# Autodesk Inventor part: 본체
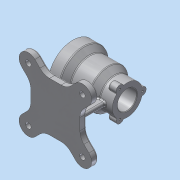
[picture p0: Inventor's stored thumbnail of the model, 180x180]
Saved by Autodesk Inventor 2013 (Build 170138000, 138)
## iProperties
Created: 2017-03
Part Number: 본체
Material: 알루미늄 6061
Document SubType Name: Modeling
Designer: Administrator
Density: 2.71 g/cm^3
Mass: 1008.07 g
Surface Area: 842.343 cm^2
Volume: 371.982 cm^3
Author: Administrator
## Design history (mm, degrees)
sketch "스케치1"
  geometry: L1 (-50, 0)-(50, 0); L2 (-50, 45)-(-30, 45); L3 (-30, 45)-(-19, 36); L4 (-19, 36)-(15, 36); L5 (15, 36)-(27, 27.5); L6 (27, 27.5)-(50, 27.5); L7 (50, 27.5)-(50, 17.5); L8 (50, 17.5)-(23, 17.5); L9 (20, 20.5)-(20, 23); L10 (17, 26)-(-24, 26); L11 (-27, 29)-(-27, 32); L12 (-30, 35)-(-50, 35); L13 (-50, 35)-(-50, 45); A1 r 3 centre (-30, 32) between (-27, 32) and (-30, 35); A2 r 3 centre (17, 23) between (20, 23) and (17, 26); A3 r 3 centre (23, 20.5) between (20, 20.5) and (23, 17.5); A4 r 3 centre (-24, 29) between (-27, 29) and (-24, 26); 5 further points
  constraints: 26 end point, 9 parallel, 8 point on circle, 8 tangent, 6 point on line, 4 centre point, 3 equal radius, 2 vertical alignment, 1 coincident, 1 horizontal, 1 midpoint, 1 perpendicular
  dimensions: "d0" = 100 distance of L1.start L1.end; "d14" = 70 diameter of L12 L1; "d15" = 52 diameter of L10 L1; "d16" = 35 diameter of L8 L1; "d17" = 23 distance of point (-27, 35) L12.end; "d18" = 47 distance of point (20, 26) point (-27, 26); "d19" = 20 distance of L2.start L2.end; "d20" = 31 distance from line of L3.end L13; "d21" = 65 distance from line of L4.end L13; "d22" = 23 distance of L5.end L6.end; "d23" = 90 diameter of L2 L1; "d24" = 72 diameter of L4 L1; "d25" = 55 diameter of L6 L1; "d26" = 3 radius of A1
revolve "회전1" sketch "스케치1" stored, may be unused: angle "d27" = 90 deg
sketch "스케치2"
  geometry: C1 r 17.5 at (0, 0) reference; C2 r 7 at (0, 27.5); 1 further point
  constraints: 2 vertical alignment, 1 centre point, 1 other
  dimensions: "d28" = 14 diameter of C2
extrude "돌출1" join sketch "스케치2" distance "d30" = 15; taper "d31" = 0 deg
fillet "모깎기1" dims "d32" = 3
fillet "모깎기2" dims "d33" = 1
sketch "스케치3"
  geometry: A1 r 7 centre (0, 0) between (6.999, -0.127) and (-6.999, -0.127) reference; 1 further point
  constraints: 1 coincident
hole "구멍1" sketch "스케치3" at (0, 0) diameter "d34" = 3.242; stored, may be unused: countersink angle "d38" = 90 deg, drill point angle "d40" = 118 deg; dims "d35" = 9, "d36" = 4, "d37" = 2, "d39" = 11
sketch "스케치4" dims "d44" = 80
  geometry: C1 r 45 at (0, 0) reference; 1 further point
  constraints: 2 vertical alignment, 2 other
hole "구멍2" sketch "스케치4" at (0, 40) diameter "d46" = 3.242; stored, may be unused: countersink angle "d50" = 90 deg, drill point angle "d52" = 118 deg; dims "d47" = 9, "d48" = 4, "d49" = 2, "d51" = 11
node "작업 평면1"
sketch "스케치5"
  geometry: L1 (45, 45)-(-45, 45); L2 (-45, 45)-(-45, -45); L3 (-45, -45)-(45, -45); L4 (45, -45)-(45, 45); L5 (45, 45)-(-45, -45); L6 (-45, 45)-(45, -45); L7 (37.477, 61.518)-(28.281, 52.322); L8 (61.518, 37.477)-(52.322, 28.281); L9 (61.518, -37.477)-(52.322, -28.281); L10 (37.477, -61.518)-(28.281, -52.322); L11 (-37.477, -61.518)-(-28.281, -52.322); L12 (-61.518, -37.477)-(-52.322, -28.281); L13 (-37.477, 61.518)-(-28.281, 52.322); L14 (-61.518, 37.477)-(-52.322, 28.281); A1 r 70 centre (0, 0) between (49.497, 49.497) and (49.497, -49.497); A2 r 17 centre (49.497, 49.497) between (37.477, 61.518) and (61.518, 37.477); A3 r 17 centre (49.497, -49.497) between (61.518, -37.477) and (37.477, -61.518); A4 r 17 centre (-49.497, -49.497) between (-37.477, -61.518) and (-61.518, -37.477); A5 r 17 centre (-49.497, 49.497) between (-37.477, 61.518) and (-61.518, 37.477); A6 r 25 centre (10.603, 70) between (10.603, 45) and (28.281, 52.322); A7 r 25 centre (70, 10.603) between (52.322, 28.281) and (45, 10.603); A8 r 25 centre (70, -10.603) between (45, -10.603) and (52.322, -28.281); A9 r 25 centre (10.603, -70) between (28.281, -52.322) and (10.603, -45); A10 r 25 centre (-70, -10.603) between (-52.322, -28.281) and (-45, -10.603); A11 r 25 centre (-10.603, 70) between (-28.281, 52.322) and (-10.603, 45); A12 r 25 centre (-70, 10.603) between (-45, 10.603) and (-52.322, 28.281); A13 r 25 centre (-10.603, -70) between (-10.603, -45) and (-28.281, -52.322); 1 further point
  constraints: 28 end point, 28 point on circle, 24 tangent, 13 centre point, 10 equal radius, 8 point on line, 6 parallel, 6 perpendicular, 2 horizontal alignment, 2 midpoint, 2 vertical alignment, 1 coincident, 1 horizontal
  dimensions: "d57" = 140 diameter of A1; "d59" = 90 deg dimension on point (0, 0) A5.centre A1.start; "d61" = 34 diameter of A2; "d62" = 90 distance of L3.end L1.start; "d63" = 25 radius of A6
extrude "돌출2" join sketch "스케치5" distance "d64" = 12; taper "d65" = 0 deg
sketch "스케치6"
  geometry: C1 r 5 at (-49.497, 49.497); C2 r 5 at (-49.497, -49.497); C3 r 5 at (49.497, -49.497); C4 r 5 at (49.497, 49.497); A1 r 17 centre (49.497, 49.497) between (61.518, 37.477) and (37.477, 61.518) reference; A2 r 17 centre (-49.497, 49.497) between (-37.477, 61.518) and (-61.518, 37.477) reference; A3 r 17 centre (-49.497, -49.497) between (-61.518, -37.477) and (-37.477, -61.518) reference; A4 r 17 centre (49.497, -49.497) between (37.477, -61.518) and (61.518, -37.477) reference; 1 further point
  constraints: 4 centre point, 4 coincident, 3 equal radius
  dimensions: "d66" = 10 diameter of C1
extrude "돌출3" cut sketch "스케치6" stored distance "d68" = 12; taper "d69" = 0 deg
fillet "모깎기3" dims "d70" = 3
sketch "스케치7"
  geometry: L1 (-70, 39.598)-(-70, 30.402) reference; L2 (-70, 10.603)-(-70, 30.402) reference; L3 (-31.096, 18.14)-(-70, 25); 2 further points
  constraints: 2 end point, 1 point on line, 2 other
  dimensions: "d71" = 100 deg angle of L3 L1; "d72" = 25 vertical distance of L3.end point (0, 0)
feature "리브1" sketch "스케치7" dims "d73" = 25, "d74" = 8, "d75" = 0, "d76" = 0, "d77" = 1, "d78" = 1
sketch "스케치8"
  geometry: L1 (-50, -45)-(-30, -45) reference; L2 (-30, -45)-(-19, -36) reference; L3 (-39.598, -70)-(-30.402, -70) reference; L4 (-10.603, -70)-(-30.402, -70) reference; L5 (-37, -45)-(-37, -70); 1 further point
  constraints: 2 end point, 2 point on line, 1 vertical
  dimensions: "d79" = 37 distance from line of L5 point (0, 0)
feature "리브2" sketch "스케치8" dims "d80" = 25, "d81" = 8, "d82" = 0, "d83" = 0, "d84" = 1, "d85" = 1
sketch "스케치9"
  geometry: L1 (4, -36)-(15, -36) reference; L2 (15, -36)-(27, -27.5) reference; L3 (30.402, -70)-(10.603, -70) reference; L4 (30.402, -70)-(39.598, -70) reference; L5 (27, -27.5)-(50, -27.5) reference; L6 (37, -27.5)-(37, -70); 1 further point
  constraints: 2 end point, 2 point on line, 1 vertical
  dimensions: "d86" = 37 distance from line of L6 point (0, 0)
feature "리브3" sketch "스케치9" dims "d87" = 25, "d88" = 8, "d89" = 0, "d90" = 0, "d91" = 1, "d92" = 1
chamfer "모따기1" distance "d93" = 1; stored, may be unused: second distance "d94" = 2, angle "d95" = 45 deg
fillet "모깎기4" dims "d96" = 3
fillet "모깎기5" dims "d97" = 3
node "작업 평면2"
sketch "스케치10"
  geometry: L1 (50, 45)-(50, -45) reference; C1 r 5 at (0, 0); 1 further point
  constraints: 1 centre point, 1 coincident
  dimensions: "d99" = 50 distance from line of C1.centre L1; "d100" = 10 diameter of C1
extrude "돌출4" join sketch "스케치10" stored distance "d101" = 12; taper "d102" = 0 deg
fillet "모깎기6" dims "d103" = 3
sketch "스케치11"
  geometry: C1 r 5 at (0, 0) reference; 1 further point
  constraints: 1 coincident
hole "구멍3" sketch "스케치11" at (0, 0) diameter "d104" = 4.134; stored, may be unused: countersink angle "d108" = 90 deg, drill point angle "d110" = 118 deg; dims "d105" = 9, "d106" = 4, "d107" = 2, "d109" = 11
sketch "스케치12"
  geometry: L1 (45, -10.603)-(45, 10.603) reference; 2 further points
  constraints: 1 other
  dimensions: "d111" = 35 distance of point (0, -35) point (0, 0); "d112" = 45 distance from line of point (0, -35) L1
feature "엠보싱1" sketch "스케치12" dims "d0" = 100, "d14" = 70, "d15" = 52, "d16" = 35, "d17" = 23, "d18" = 47, "d19" = 20, "d20" = 31, "d21" = 65, "d22" = 23, "d23" = 90, "d24" = 72, "d25" = 55, "d26" = 3, "d113" = 0.5, "d114" = 0
node "솔리드1"
pattern_circular "원형 패턴1" dims "d42" = 360 deg
pattern_circular "원형 패턴2" dims angle "d54" = 360 deg
mirror "대칭1"
other parameters: "d56" = -82
